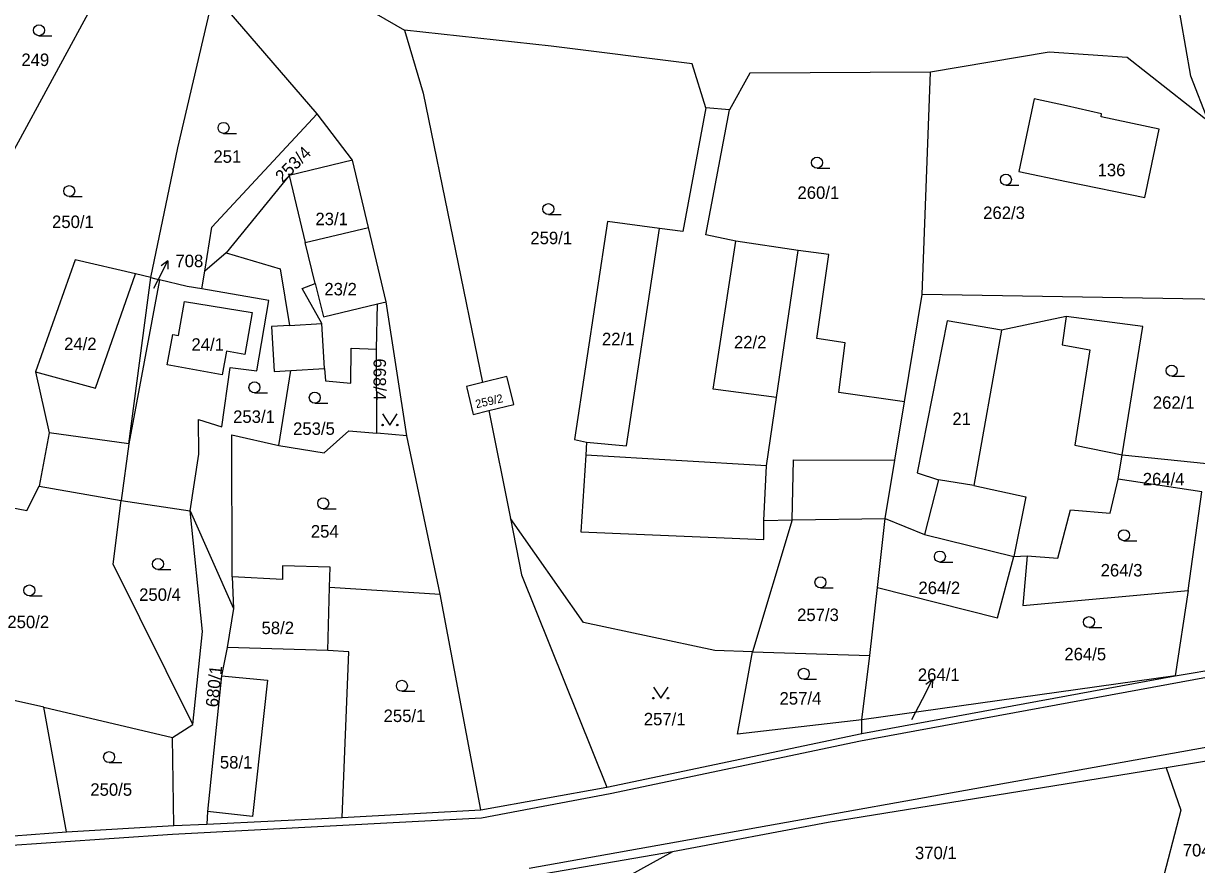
# Model space of a CAD drawing. Extents: x -7483133 to -743169, y -11317770 to -1127091.
# Drawn here: x -746401 to -746241.3, y -1132326.3 to -1132211.8 of the extents above; entities that cross this region are included whole.
import ezdxf

# ---------------------------------------------------------------- set-up
doc = ezdxf.new("R2010")
doc.units = 0
for name, color, linetype in [('Hranice parcel', 7, 'Continuous'), ('Parcelní čísla', 7, 'Continuous'), ('Pop  PČ popisy', 7, 'Continuous'), ('Vnitřní kresba', 7, 'Continuous'), ('Značky kultur', 7, 'Continuous')]:
    doc.layers.add(name, color=color, linetype=linetype)

msp = doc.modelspace()

# ---------------------------------------------------------------- linework, layer by layer
at = {"layer": 'Hranice parcel'}
for p, q in [((-746385.31, -1132191.74), (-746349.14, -1132212.69)), ((-746402.53, -1132229.49), (-746387.86, -1132202.51)), ((-746278.68, -1132248.7), (-746277.54, -1132218.41)), ((-746304.89, -1132223.54), (-746308.1, -1132223.28)), ((-746356.19, -1132230.43), (-746361.01, -1132224.1)), ((-746354.02, -1132239.56), (-746356.19, -1132230.43)), ((-746351.62, -1132249.69), (-746354.02, -1132239.56)), ((-746373.4, -1132243.01), (-746376.31, -1132245.54)), ((-746376.71, -1132247.95), (-746376.31, -1132245.54)), ((-746386.66, -1132269.02), (-746383.65, -1132246.38)), ((-746382.45, -1132246.69), (-746386.66, -1132269.02)), ((-746383.65, -1132246.38), (-746382.45, -1132246.69)), ((-746367.58, -1132249.53), (-746376.71, -1132247.95)), ((-746281.1, -1132263.3), (-746278.68, -1132248.7)), ((-746236.8, -1132249.39), (-746278.68, -1132248.7)), ((-746369.24, -1132259.11), (-746367.58, -1132249.53)), ((-746348.82, -1132267.93), (-746351.62, -1132249.69)), ((-746352.9, -1132267.59), (-746352.94, -1132256.15)), ((-746366.22, -1132269.26), (-746364.59, -1132259.06)), ((-746364.59, -1132259.06), (-746360, -1132258.78)), ((-746337.67, -1132264.5), (-746334.69, -1132279.22)), ((-746348.82, -1132267.93), (-746352.9, -1132267.59)), ((-746344.28, -1132289.52), (-746348.82, -1132267.93)), ((-746386.66, -1132269.02), (-746387.66, -1132276.75)), ((-746252, -1132273.84), (-746251.48, -1132270.51)), ((-746251.48, -1132270.51), (-746239.94, -1132271.7)), ((-746240.62, -1132275.55), (-746252, -1132273.84)), ((-746398.85, -1132274.79), (-746387.66, -1132276.75)), ((-746242.47, -1132288.99), (-746240.62, -1132275.55)), ((-746387.66, -1132276.75), (-746378.28, -1132278.15)), ((-746378.28, -1132278.15), (-746372.39, -1132291.44)), ((-746296.38, -1132279.4), (-746301.77, -1132297.36)), ((-746300.23, -1132279.48), (-746296.38, -1132279.4)), ((-746296.38, -1132279.4), (-746283.73, -1132279.22)), ((-746284.76, -1132288.58), (-746283.73, -1132279.22)), ((-746283.73, -1132279.22), (-746278.34, -1132281.37)), ((-746278.34, -1132281.37), (-746266.19, -1132284.36)), ((-746266.19, -1132284.36), (-746264.4, -1132284.28)), ((-746372.56, -1132287.12), (-746372.39, -1132291.44)), ((-746359.56, -1132297.17), (-746359.35, -1132288.57)), ((-746359.35, -1132288.57), (-746344.28, -1132289.52)), ((-746285.78, -1132297.87), (-746284.76, -1132288.58)), ((-746242.47, -1132288.99), (-746244.25, -1132300.62)), ((-746338.75, -1132318.87), (-746344.28, -1132289.52)), ((-746372.39, -1132291.44), (-746373.25, -1132296.77)), ((-746359.56, -1132297.17), (-746373.25, -1132296.77)), ((-746301.77, -1132297.36), (-746285.78, -1132297.87)), ((-746286.89, -1132306.6), (-746285.78, -1132297.87)), ((-746398.2, -1132304.9), (-746422.09, -1132299.47)), ((-746244.25, -1132300.62), (-746234.67, -1132298.99)), ((-746244.25, -1132300.62), (-746286.89, -1132306.6)), ((-746286.89, -1132308.48), (-746244.25, -1132300.62)), ((-746398.2, -1132304.9), (-746380.7, -1132309.01)), ((-746395.13, -1132321.84), (-746398.2, -1132304.9)), ((-746286.89, -1132308.48), (-746286.89, -1132306.6)), ((-746380.7, -1132309.01), (-746377.93, -1132307.24)), ((-746380.5, -1132320.99), (-746380.7, -1132309.01)), ((-746321.59, -1132315.77), (-746286.89, -1132308.48)), ((-746236.32, -1132311.64), (-746245.46, -1132313.16)), ((-746245.46, -1132313.16), (-746243.49, -1132318.9)), ((-746338.75, -1132318.87), (-746321.59, -1132315.77)), ((-746357.62, -1132319.89), (-746338.75, -1132318.87)), ((-746243.49, -1132318.9), (-746246.67, -1132331.25)), ((-746395.13, -1132321.84), (-746380.5, -1132320.99)), ((-746380.5, -1132320.99), (-746376.02, -1132320.81)), ((-746376.02, -1132320.81), (-746357.62, -1132319.89)), ((-746312.67, -1132324.59), (-746331.35, -1132327.82))]:
    msp.add_line(p, q, dxfattribs=at)
for points in [[(-746239.72, -1132225.13), (-746242.13, -1132218.98), (-746247.56, -1132187.7), (-746250.26, -1132174.19)], [(-746383.65, -1132246.38), (-746379.95, -1132228.73), (-746375.2, -1132208.32)], [(-746361.01, -1132224.1), (-746374.1, -1132208.89), (-746375.2, -1132208.32)], [(-746308.1, -1132223.28), (-746309.97, -1132217.3), (-746329.17, -1132214.87), (-746349.14, -1132212.69)], [(-746349.14, -1132212.69), (-746346.6, -1132221.28), (-746338.5, -1132260.67)], [(-746239.72, -1132225.13), (-746250.79, -1132216.43), (-746261.41, -1132215.72), (-746277.54, -1132218.41)], [(-746277.54, -1132218.41), (-746302.15, -1132218.58), (-746304.89, -1132223.54)], [(-746308.1, -1132223.28), (-746311.26, -1132240.14), (-746314.42, -1132239.71), (-746321.52, -1132238.77), (-746325.97, -1132268.44), (-746324.34, -1132268.79), (-746324.45, -1132270.59), (-746325.11, -1132281.02), (-746300.23, -1132282.05), (-746300.23, -1132279.48)], [(-746304.05, -1132241.46), (-746308.13, -1132240.56), (-746304.89, -1132223.54)], [(-746263.45, -1132222.08), (-746265.54, -1132231.97), (-746259.04, -1132233.31), (-746248.37, -1132235.5), (-746246.42, -1132226.19), (-746254.34, -1132224.51), (-746254.26, -1132224.12)], [(-746254.26, -1132224.12), (-746259.05, -1132223), (-746263.45, -1132222.08)], [(-746376.31, -1132245.54), (-746375.33, -1132239.55), (-746361.01, -1132224.1)], [(-746356.19, -1132230.43), (-746364.83, -1132232.5), (-746373.4, -1132243.01)], [(-746361.26, -1132247.22), (-746362.62, -1132241.61), (-746354.02, -1132239.56)], [(-746300.23, -1132279.48), (-746299.84, -1132272.04), (-746298.48, -1132262.72), (-746307.11, -1132261.61), (-746304.05, -1132241.46)], [(-746281.1, -1132263.3), (-746290.01, -1132262.04), (-746289.16, -1132255.28), (-746293, -1132254.68), (-746291.36, -1132243.25), (-746295.57, -1132242.7), (-746304.05, -1132241.46)], [(-746383.65, -1132246.38), (-746385.74, -1132245.89), (-746393.93, -1132243.96), (-746399.35, -1132259.24), (-746397.47, -1132267.55), (-746398.85, -1132274.79)], [(-746373.4, -1132243.01), (-746366.05, -1132245.19), (-746364.79, -1132252.91), (-746367.22, -1132253.06)], [(-746376.71, -1132247.95), (-746378.69, -1132247.61), (-746382.45, -1132246.69)], [(-746360, -1132258.78), (-746360.38, -1132252.64), (-746363.05, -1132247.88), (-746361.26, -1132247.22)], [(-746352.94, -1132256.15), (-746352.78, -1132249.96), (-746351.62, -1132249.69)], [(-746251.48, -1132270.51), (-746248.66, -1132253.06), (-746259.09, -1132251.69), (-746267.9, -1132253.57), (-746275.26, -1132252.29), (-746279.36, -1132272.99), (-746276.45, -1132273.93), (-746278.34, -1132281.37)], [(-746367.22, -1132253.06), (-746366.84, -1132259.2), (-746364.59, -1132259.06)], [(-746360, -1132258.78), (-746359.86, -1132260.47), (-746356.42, -1132260.75), (-746356.38, -1132256.01), (-746352.94, -1132256.15)], [(-746378.28, -1132278.15), (-746377.13, -1132270.44), (-746377.15, -1132265.72), (-746373.96, -1132266.7), (-746372.85, -1132258.64), (-746369.24, -1132259.11)], [(-746337.67, -1132264.5), (-746334.26, -1132263.66), (-746334.31, -1132263.47), (-746335.15, -1132260.05), (-746335.2, -1132259.86), (-746338.5, -1132260.67)], [(-746338.5, -1132260.67), (-746340.67, -1132261.21), (-746340.62, -1132261.4), (-746339.84, -1132264.84), (-746339.8, -1132265.03), (-746337.67, -1132264.5)], [(-746283.73, -1132279.22), (-746282.42, -1132271.26), (-746281.1, -1132263.3)], [(-746372.56, -1132287.12), (-746372.62, -1132267.81), (-746366.22, -1132269.26)], [(-746366.22, -1132269.26), (-746360.07, -1132270.26), (-746356.7, -1132267.27), (-746352.9, -1132267.59)], [(-746264.4, -1132284.28), (-746260.21, -1132284.62), (-746258.5, -1132278.03), (-746253.11, -1132278.46), (-746252, -1132273.84)], [(-746416.68, -1132275.01), (-746400.51, -1132278.11), (-746398.85, -1132274.79)], [(-746377.93, -1132307.24), (-746388.78, -1132285.42), (-746387.66, -1132276.75)], [(-746377.93, -1132307.24), (-746376.62, -1132294.6), (-746378.28, -1132278.15)], [(-746301.77, -1132297.36), (-746306.9, -1132297.19), (-746324.77, -1132293.34), (-746334.69, -1132279.22)], [(-746334.69, -1132279.22), (-746333.21, -1132286.86), (-746321.59, -1132315.77)], [(-746264.4, -1132284.28), (-746265, -1132291.03), (-746242.47, -1132288.99)], [(-746359.35, -1132288.57), (-746359.26, -1132285.83), (-746365.72, -1132285.66), (-746365.72, -1132287.5), (-746372.56, -1132287.12)], [(-746284.76, -1132288.58), (-746268.42, -1132292.74), (-746266.19, -1132284.36)], [(-746373.25, -1132296.77), (-746374.02, -1132300.61), (-746375.92, -1132319.08), (-746376.02, -1132320.81)], [(-746357.62, -1132319.89), (-746356.71, -1132297.35), (-746359.56, -1132297.17)], [(-746286.89, -1132306.6), (-746303.82, -1132308.56), (-746301.77, -1132297.36)], [(-746245.46, -1132313.16), (-746291.48, -1132320.59), (-746312.67, -1132324.59)], [(-746427.94, -1132325.8), (-746420.34, -1132325.03), (-746404.78, -1132322.59), (-746395.13, -1132321.84)], [(-746312.67, -1132324.59), (-746321.38, -1132329.41), (-746329.35, -1132338.1)]]:
    msp.add_lwpolyline(points, dxfattribs=at)
at = {"layer": 'Pop  PČ popisy'}
for p, q in [((-746382.68, -1132246.79), (-746381.32, -1132244.12)), ((-746381.32, -1132244.12), (-746382.22, -1132244.78)), ((-746381.32, -1132244.12), (-746381.33, -1132245.24)), ((-746383.22, -1132247.84), (-746382.68, -1132246.79)), ((-746278.65, -1132303.81), (-746277.29, -1132301.14)), ((-746277.29, -1132301.14), (-746278.19, -1132301.8)), ((-746277.29, -1132301.14), (-746277.3, -1132302.26)), ((-746280.07, -1132306.57), (-746278.65, -1132303.81))]:
    msp.add_line(p, q, dxfattribs=at)
at = {"layer": 'Vnitřní kresba'}
for p, q in [((-746364.83, -1132232.5), (-746362.62, -1132241.61)), ((-746318.91, -1132269.3), (-746314.42, -1132239.71)), ((-746298.48, -1132262.72), (-746295.57, -1132242.7)), ((-746391.16, -1132261.46), (-746385.74, -1132245.89)), ((-746361.26, -1132247.22), (-746360.17, -1132251.72)), ((-746360.17, -1132251.72), (-746352.78, -1132249.96)), ((-746259.09, -1132251.69), (-746259.61, -1132255.54)), ((-746364.79, -1132252.91), (-746360.38, -1132252.64)), ((-746267.9, -1132253.57), (-746271.66, -1132274.7)), ((-746259.61, -1132255.54), (-746255.84, -1132256.22)), ((-746255.84, -1132256.22), (-746257.9, -1132269.22)), ((-746399.35, -1132259.24), (-746391.16, -1132261.46)), ((-746386.66, -1132269.02), (-746397.47, -1132267.55)), ((-746324.34, -1132268.79), (-746318.91, -1132269.3)), ((-746257.9, -1132269.22), (-746251.48, -1132270.51)), ((-746299.84, -1132272.04), (-746324.45, -1132270.59)), ((-746296.38, -1132279.4), (-746296.17, -1132271.19)), ((-746296.17, -1132271.19), (-746282.42, -1132271.26)), ((-746271.66, -1132274.7), (-746276.45, -1132273.93)), ((-746271.66, -1132274.7), (-746264.57, -1132276.24)), ((-746264.57, -1132276.24), (-746266.19, -1132284.36)), ((-746193.54, -1132292.28), (-746287.05, -1132309.52)), ((-746374.02, -1132300.61), (-746367.75, -1132301.19)), ((-746367.75, -1132301.19), (-746369.8, -1132319.75)), ((-746332.14, -1132326.83), (-746231.85, -1132308.88)), ((-746287.05, -1132309.52), (-746321.12, -1132316.7)), ((-746321.12, -1132316.7), (-746338.63, -1132320.01)), ((-746369.8, -1132319.75), (-746375.92, -1132319.08)), ((-746338.63, -1132320.01), (-746380.7, -1132322.22)), ((-746380.7, -1132322.22), (-746404.7, -1132323.87))]:
    msp.add_line(p, q, dxfattribs=at)
msp.add_lwpolyline([(-746379.07, -1132249.64), (-746369.84, -1132251.15), (-746370.87, -1132256.87), (-746373.34, -1132256.42), (-746373.93, -1132259.62), (-746381.42, -1132258.26), (-746380.65, -1132254.15), (-746379.86, -1132254.3), (-746379.07, -1132249.64)], dxfattribs=at)
at = {"layer": 'Značky kultur'}
for p, q in [((-746398.87, -1132213.47), (-746397.12, -1132213.47)), ((-746373.75, -1132226.76), (-746372, -1132226.76)), ((-746292.99, -1132231.5), (-746291.24, -1132231.5)), ((-746267.29, -1132233.81), (-746265.54, -1132233.81)), ((-746394.75, -1132235.37), (-746393, -1132235.37)), ((-746329.55, -1132237.82), (-746327.8, -1132237.82)), ((-746244.72, -1132259.81), (-746242.97, -1132259.81)), ((-746369.54, -1132262.09), (-746367.79, -1132262.09)), ((-746361.33, -1132263.49), (-746359.58, -1132263.49)), ((-746360.19, -1132277.88), (-746358.44, -1132277.88)), ((-746251.22, -1132282.22), (-746249.47, -1132282.22)), ((-746276.27, -1132285.13), (-746274.52, -1132285.13)), ((-746382.67, -1132286.15), (-746380.92, -1132286.15)), ((-746292.52, -1132288.63), (-746290.77, -1132288.63)), ((-746400.17, -1132289.74), (-746398.42, -1132289.74)), ((-746255.97, -1132294.06), (-746254.22, -1132294.06)), ((-746294.79, -1132301.09), (-746293.04, -1132301.09)), ((-746349.48, -1132302.73), (-746347.73, -1132302.73)), ((-746389.32, -1132312.44), (-746387.57, -1132312.44))]:
    msp.add_line(p, q, dxfattribs=at)
for points in [[(-746352.11, -1132264.97), (-746351.11, -1132266.47), (-746350.11, -1132264.97)], [(-746315.26, -1132302.16), (-746314.26, -1132303.66), (-746313.26, -1132302.16)]]:
    msp.add_lwpolyline(points, dxfattribs=at)
for centre, radius in [((-746398.87, -1132212.72), 0.75), ((-746373.75, -1132226.01), 0.75), ((-746292.99, -1132230.75), 0.75), ((-746267.29, -1132233.06), 0.75), ((-746394.75, -1132234.62), 0.75), ((-746329.55, -1132237.07), 0.75), ((-746244.72, -1132259.06), 0.75), ((-746369.54, -1132261.34), 0.75), ((-746361.33, -1132262.74), 0.75), ((-746352.11, -1132266.47), 0.1), ((-746350.11, -1132266.47), 0.1), ((-746360.19, -1132277.13), 0.75), ((-746251.22, -1132281.47), 0.75), ((-746276.27, -1132284.38), 0.75), ((-746382.67, -1132285.4), 0.75), ((-746292.52, -1132287.88), 0.75), ((-746400.17, -1132288.99), 0.75), ((-746255.97, -1132293.31), 0.75), ((-746294.79, -1132300.34), 0.75), ((-746349.48, -1132301.98), 0.75), ((-746315.26, -1132303.66), 0.1), ((-746313.26, -1132303.66), 0.1), ((-746389.32, -1132311.69), 0.75)]:
    msp.add_circle(centre, radius, dxfattribs=at)

# ---------------------------------------------------------------- texts
at = {"layer": 'Parcelní čísla'}
for s, p in [('249', (-746401.26, -1132217.59)), ('251', (-746375.13, -1132230.77)), ('136', (-746254.81, -1132232.6)), ('260/1', (-746295.65, -1132235.68)), ('250/1', (-746397.09, -1132239.65)), ('23/1', (-746361.25, -1132239.26)), ('262/3', (-746270.38, -1132238.42)), ('259/1', (-746332, -1132241.85)), ('708', (-746380.3, -1132244.98)), ('23/2', (-746360.03, -1132248.82)), ('22/1', (-746322.25, -1132255.61)), ('24/2', (-746395.45, -1132256.27)), ('24/1', (-746378.12, -1132256.36)), ('22/2', (-746304.29, -1132256.04)), ('262/1', (-746247.29, -1132264.26)), ('253/1', (-746372.45, -1132266.18)), ('21', (-746274.57, -1132266.48)), ('253/5', (-746364.29, -1132267.81)), ('264/4', (-746248.66, -1132274.69)), ('254', (-746361.87, -1132281.8)), ('264/3', (-746254.39, -1132287.09)), ('250/4', (-746385.24, -1132290.41)), ('264/2', (-746279.19, -1132289.49)), ('257/3', (-746295.7, -1132293.16)), ('250/2', (-746403.17, -1132294.13)), ('58/2', (-746368.58, -1132294.94)), ('264/5', (-746259.33, -1132298.51)), ('264/1', (-746279.27, -1132301.32)), ('257/4', (-746298.09, -1132304.54)), ('255/1', (-746351.97, -1132306.91)), ('257/1', (-746316.56, -1132307.36)), ('58/1', (-746374.25, -1132313.24)), ('250/5', (-746391.88, -1132316.95)), ('370/1', (-746279.66, -1132325.58)), ('704/31', (-746243.22, -1132325.21))]:
    msp.add_text(s, height=1.7, dxfattribs=at).set_placement(p)
for s, height, rotation, p in [('253/4', 1.7, 45, (-746365.7, -1132233.59)), ('668/4', 1.7, 270, (-746353.34, -1132257.42)), ('259/2', 1.14, 13, (-746339.34, -1132264.2)), ('680/1', 1.7, 84, (-746374.51, -1132304.96))]:
    msp.add_text(s, height=height, rotation=rotation, dxfattribs=at).set_placement(p)

doc.saveas('drawing.dxf')
